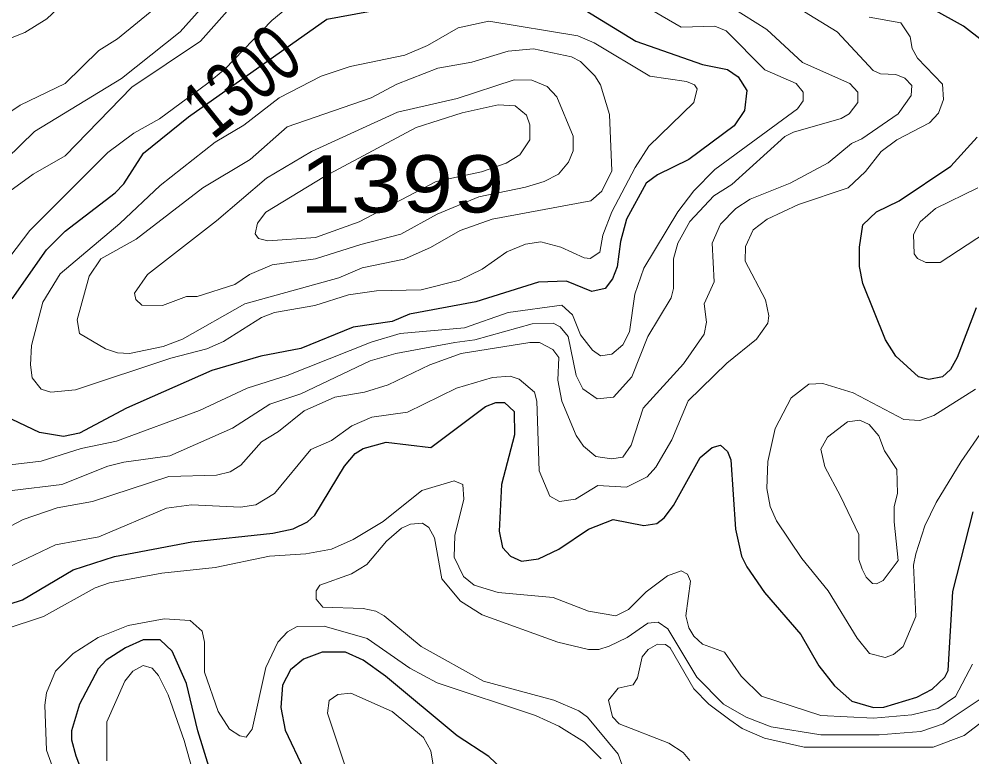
# Model space of a CAD drawing. Extents: x 577 to 602.9, y 7483.8 to 7511.6.
# Drawn here: x 580.554 to 581.886, y 7485.838 to 7486.869 of the extents above; entities that cross this region are included whole.
import ezdxf
from ezdxf.enums import TextEntityAlignment as Align

# ---------------------------------------------------------------- set-up
doc = ezdxf.new("R2010")
doc.units = 0
doc.header["$LTSCALE"] = 0.032
doc.layers.add('1', color=7, linetype='Continuous', lineweight=25)
doc.layers.add('2', color=7, linetype='Continuous', lineweight=13)
doc.layers.add('61', color=7, linetype='Continuous')

msp = doc.modelspace()

# ---------------------------------------------------------------- linework, layer by layer
at = {"layer": '1'}
for points in [[(581.3451, 7486.881), (581.4159, 7486.838), (581.5089, 7486.8054), (581.5439, 7486.7983), (581.559, 7486.7879), (581.5709, 7486.7688), (581.5677, 7486.741), (581.5534, 7486.7195), (581.4898, 7486.6726), (581.4461, 7486.6512), (581.4302, 7486.6392), (581.4031, 7486.5891), (581.3944, 7486.5581), (581.3896, 7486.5223), (581.3833, 7486.5056), (581.3729, 7486.4921), (581.3546, 7486.4881), (581.3189, 7486.5025), (581.2799, 7486.5009), (581.1924, 7486.4738), (581.0994, 7486.4563), (581.0755, 7486.446), (581.0207, 7486.438), (580.9475, 7486.4086), (580.8918, 7486.3975), (580.8235, 7486.3776), (580.7042, 7486.3251), (580.6382, 7486.2901), (580.6159, 7486.2854), (580.5825, 7486.2909), (580.5444, 7486.3092)], [(580.5444, 7486.4778), (580.5921, 7486.5462), (580.6183, 7486.5724), (580.6883, 7486.6257), (580.7002, 7486.6384), (580.728, 7486.6814), (580.7905, 7486.7319), (580.984, 7486.8685), (581.0421, 7486.8794)], [(581.9009, 7486.838), (581.8739, 7486.8587), (581.831, 7486.8826)], [(581.8914, 7486.4651), (581.8651, 7486.3959), (581.8556, 7486.3792), (581.8445, 7486.3689), (581.8254, 7486.3649), (581.8111, 7486.3689), (581.7793, 7486.3975), (581.765, 7486.4206), (581.7331, 7486.4993), (581.7284, 7486.5231), (581.7284, 7486.5502), (581.7331, 7486.5812), (581.7522, 7486.5995), (581.784, 7486.6146), (581.8564, 7486.6631), (581.893, 7486.7036)], [(580.4863, 7486.0341), (580.5587, 7486.0572), (580.6294, 7486.0993), (580.6875, 7486.1176), (580.7956, 7486.1383), (580.9085, 7486.1502), (580.9372, 7486.1566), (580.9571, 7486.1661), (580.9674, 7486.1756), (581.0087, 7486.244), (581.0238, 7486.2615), (581.035, 7486.2687), (581.0668, 7486.2774), (581.1296, 7486.2703), (581.2059, 7486.3275), (581.2203, 7486.3331), (581.2322, 7486.3331), (581.2457, 7486.3204), (581.2465, 7486.2878), (581.2282, 7486.2186), (581.225, 7486.1534), (581.2298, 7486.1303), (581.2409, 7486.1184), (581.256, 7486.1112), (581.2799, 7486.1144), (581.3085, 7486.1279), (581.3499, 7486.1558), (581.3841, 7486.1693), (581.427, 7486.1613), (581.4453, 7486.1637), (581.4556, 7486.1717), (581.4684, 7486.1892), (581.5057, 7486.256), (581.5224, 7486.2703), (581.5344, 7486.2734), (581.5439, 7486.2647), (581.5487, 7486.2528), (581.555, 7486.1558), (581.5638, 7486.1184), (581.5709, 7486.1033), (581.5956, 7486.0675), (581.6465, 7486.0087), (581.6719, 7485.9649), (581.6934, 7485.9371), (581.718, 7485.9156), (581.748, 7485.907), (581.7626, 7485.9075), (581.8087, 7485.9212), (581.8302, 7485.9323), (581.8476, 7485.949), (581.8524, 7485.9586), (581.8588, 7486.0691), (581.8874, 7486.1804)], [(580.8314, 7485.7852), (580.8036, 7485.8743), (580.7877, 7485.9403), (580.7678, 7485.9856), (580.7511, 7486.0015), (580.7272, 7486.0015), (580.7026, 7485.9904), (580.6756, 7485.9729), (580.6644, 7485.9609), (580.6382, 7485.9116), (580.6271, 7485.8743), (580.6271, 7485.8615), (580.6334, 7485.8393), (580.6644, 7485.7574)], [(581.2298, 7485.8202), (581.2107, 7485.8385), (581.1662, 7485.8671), (581.066, 7485.9506), (581.035, 7485.9729), (581.0103, 7485.984), (580.9777, 7485.984), (580.9515, 7485.9745), (580.9332, 7485.9594), (580.9221, 7485.9379), (580.9197, 7485.9069), (580.926, 7485.8751), (580.9515, 7485.821)]]:
    msp.add_lwpolyline(points, dxfattribs=at)
at = {"layer": '2'}
for points in [[(580.5364, 7487.2062), (580.5618, 7487.2054), (580.5817, 7487.1974), (580.5976, 7487.1784), (580.5992, 7487.1418), (580.604, 7487.1275), (580.6271, 7487.1036), (580.6692, 7487.0726), (580.7026, 7487.0599), (580.732, 7487.0551), (580.7789, 7487.0535), (580.8044, 7487.0472), (580.8243, 7487.0368), (580.8346, 7487.0249), (580.8378, 7487.0042), (580.829, 7486.9827), (580.7781, 7486.9167), (580.7424, 7486.8826), (580.6915, 7486.8412), (580.6652, 7486.8245), (580.6183, 7486.7784), (580.5555, 7486.7482), (580.4895, 7486.7036)], [(580.4784, 7486.8166), (580.5618, 7486.8499), (580.5929, 7486.869), (580.6294, 7486.904), (580.6438, 7486.9342), (580.6684, 7486.9676), (580.6692, 7486.9867), (580.6652, 7486.9994), (580.6461, 7487.0241), (580.6143, 7487.0503), (580.5881, 7487.0869), (580.5603, 7487.1147), (580.5467, 7487.1235)], [(580.9523, 7487.001), (580.8076, 7486.838), (580.7113, 7486.7736), (580.6183, 7486.6774), (580.5738, 7486.6519), (580.5308, 7486.6209)], [(581.4206, 7486.8913), (581.4795, 7486.8571), (581.5264, 7486.8587), (581.5423, 7486.8523), (581.5964, 7486.7975), (581.6401, 7486.7784), (581.6497, 7486.7665), (581.6497, 7486.7545), (581.6417, 7486.7434), (581.5264, 7486.6583), (581.497, 7486.6289), (581.4747, 7486.5995), (581.427, 7486.5207), (581.4143, 7486.4842), (581.4071, 7486.4317), (581.3976, 7486.4134), (581.3825, 7486.4007), (581.3666, 7486.3983), (581.3554, 7486.4062), (581.3387, 7486.4277), (581.3276, 7486.4555), (581.3125, 7486.4691), (581.2377, 7486.4587), (581.1765, 7486.4373), (581.0867, 7486.4293), (581.0461, 7486.4174), (580.9284, 7486.3705), (580.8728, 7486.353), (580.806, 7486.322), (580.6899, 7486.279), (580.6406, 7486.2687), (580.5849, 7486.2512), (580.5173, 7486.2432)], [(580.5213, 7486.5112), (580.569, 7486.5732), (580.6779, 7486.6822), (580.7145, 7486.7092), (580.7503, 7486.7291), (580.8177, 7486.7793), (580.8413, 7486.7987), (580.9071, 7486.8667), (580.9331, 7486.8881)], [(581.163, 7486.4166), (581.1908, 7486.4206), (581.2711, 7486.4428), (581.3006, 7486.4436), (581.3101, 7486.4388), (581.3212, 7486.4253), (581.3324, 7486.3705), (581.3419, 7486.3522), (581.3618, 7486.3379), (581.3849, 7486.3402), (581.4103, 7486.3689), (581.4326, 7486.4253), (581.4652, 7486.4794), (581.4684, 7486.4921), (581.4684, 7486.5335), (581.4747, 7486.5557), (581.4914, 7486.5859), (581.5248, 7486.6217), (581.5503, 7486.6376), (581.6242, 7486.7044), (581.6361, 7486.7108), (581.7029, 7486.7299), (581.7141, 7486.7362), (581.726, 7486.7521), (581.726, 7486.7665), (581.7149, 7486.7784), (581.6489, 7486.8078), (581.5988, 7486.8539), (581.5336, 7486.8953)], [(581.6433, 7486.8841), (581.6974, 7486.8507), (581.7475, 7486.7967), (581.7578, 7486.7919), (581.7793, 7486.7911), (581.792, 7486.7863), (581.8015, 7486.776), (581.8007, 7486.7617), (581.7824, 7486.7362), (581.7316, 7486.7013), (581.7172, 7486.6949), (581.6846, 7486.6679), (581.6314, 7486.6392), (581.5757, 7486.617), (581.5558, 7486.6042), (581.5344, 7486.582), (581.5224, 7486.5557), (581.5256, 7486.5017), (581.5113, 7486.4706), (581.5145, 7486.4452), (581.5113, 7486.4285), (581.4827, 7486.3872), (581.4262, 7486.3251), (581.4095, 7486.2734), (581.3976, 7486.2567), (581.3817, 7486.2544), (581.3602, 7486.2575), (581.3427, 7486.2719), (581.3324, 7486.287), (581.3125, 7486.3347), (581.3069, 7486.3641), (581.3085, 7486.3959), (581.2998, 7486.407), (581.2815, 7486.4166), (581.268, 7486.4166), (581.1717, 7486.4015)], [(580.5165, 7486.6543), (580.5754, 7486.7116), (580.697, 7486.7855), (580.7789, 7486.8507), (580.8068, 7486.8818)], [(581.6003, 7486.4436), (581.6019, 7486.454), (581.5972, 7486.4762), (581.5685, 7486.5303), (581.5693, 7486.551), (581.5797, 7486.574), (581.5996, 7486.5891), (581.6433, 7486.6098), (581.7125, 7486.6329), (581.7371, 7486.6559), (581.7586, 7486.6838), (581.7809, 7486.6997), (581.8262, 7486.7235), (581.8389, 7486.737), (581.8461, 7486.7561), (581.8445, 7486.7776), (581.8095, 7486.8142), (581.8023, 7486.8277), (581.7991, 7486.8436), (581.7864, 7486.8635), (581.7419, 7486.8714)], [(581.9303, 7486.5867), (581.8413, 7486.5287), (581.8214, 7486.5287), (581.8095, 7486.5343), (581.8047, 7486.5406), (581.8039, 7486.5677), (581.8135, 7486.5852), (581.8349, 7486.6042), (581.8938, 7486.6329)], [(580.5165, 7486.0921), (580.6048, 7486.1343), (580.6652, 7486.1454), (580.7598, 7486.1852), (580.7948, 7486.19), (580.8632, 7486.1868), (580.8847, 7486.19), (580.9109, 7486.2059), (580.9618, 7486.2671), (580.9904, 7486.2798), (581.0191, 7486.3005), (581.0469, 7486.3124), (581.097, 7486.3196), (581.1654, 7486.353), (581.2155, 7486.3681), (581.2401, 7486.3697), (581.2529, 7486.3657), (581.2743, 7486.3474), (581.2775, 7486.3347), (581.2807, 7486.2377), (581.2958, 7486.2019), (581.3093, 7486.1947), (581.3316, 7486.1979), (581.3626, 7486.217), (581.4031, 7486.2146), (581.4318, 7486.2289), (581.4437, 7486.2424), (581.466, 7486.2806), (581.489, 7486.3355), (581.5431, 7486.388), (581.5844, 7486.4213), (581.6003, 7486.4436)], [(580.5444, 7486.2098), (580.6135, 7486.2186), (580.6779, 7486.244), (580.7002, 7486.2496), (580.7646, 7486.2583), (580.8521, 7486.2973), (580.9046, 7486.3307), (580.9475, 7486.345), (581.0445, 7486.3911), (581.0803, 7486.4015), (581.163, 7486.4166)], [(581.1717, 7486.4015), (581.128, 7486.3856), (581.07, 7486.3577), (581.0366, 7486.3474), (580.9952, 7486.3402), (580.9523, 7486.3212), (580.9165, 7486.2925), (580.8926, 7486.2782), (580.864, 7486.2456), (580.8489, 7486.2361), (580.8298, 7486.2313), (580.763, 7486.2297), (580.6565, 7486.1947), (580.6072, 7486.186), (580.5595, 7486.1693), (580.4895, 7486.1327)], [(581.8906, 7486.3514), (581.8325, 7486.3148), (581.8127, 7486.3076), (581.7904, 7486.3092), (581.7196, 7486.3466), (581.6775, 7486.3593), (581.6576, 7486.3585), (581.633, 7486.3394), (581.6107, 7486.2965), (581.6003, 7486.2504), (581.5988, 7486.213), (581.6035, 7486.1876), (581.6123, 7486.1677), (581.6481, 7486.1152), (581.6846, 7486.0699), (581.7252, 7486.0039), (581.7427, 7485.9824), (581.7642, 7485.9768), (581.7761, 7485.9808), (581.7896, 7485.992), (581.8071, 7486.0341), (581.8039, 7486.1057), (581.8071, 7486.1216), (581.8198, 7486.1605), (581.8357, 7486.1931), (581.8707, 7486.2504), (581.9311, 7486.3379)], [(580.5332, 7486.0158), (580.5881, 7486.0341), (580.6605, 7486.0739), (580.6803, 7486.081), (580.7535, 7486.0945), (580.8282, 7486.1025), (580.9038, 7486.1184), (580.9547, 7486.1216), (580.9904, 7486.1279), (581.0207, 7486.1414), (581.0628, 7486.1669), (581.1169, 7486.2098), (581.1622, 7486.2233), (581.1741, 7486.2186), (581.1757, 7486.1979), (581.163, 7486.147), (581.1622, 7486.1168), (581.1749, 7486.0898), (581.19, 7486.0778), (581.2234, 7486.0675), (581.3006, 7486.0603), (581.3499, 7486.0413), (581.388, 7486.0349), (581.4055, 7486.0436), (581.4302, 7486.0683), (581.4604, 7486.0906), (581.4795, 7486.0977), (581.4882, 7486.0929), (581.4922, 7486.0834), (581.4858, 7486.0349), (581.4898, 7486.0182), (581.497, 7486.0063), (581.5089, 7485.9951), (581.5399, 7485.984), (581.563, 7485.9506), (581.5916, 7485.9228), (581.6743, 7485.8957), (581.7483, 7485.8918), (581.8015, 7485.8965), (581.8381, 7485.9053), (581.8628, 7485.922)], [(581.4047, 7485.8043), (581.3912, 7485.8417), (581.3483, 7485.8934), (581.3364, 7485.9021), (581.3014, 7485.9172), (581.2028, 7485.9434), (581.1161, 7485.992), (581.0644, 7486.0349), (581.0525, 7486.0413), (581.035, 7486.0452), (580.9785, 7486.0468), (580.969, 7486.058), (580.969, 7486.0699), (580.9745, 7486.0778), (581.0183, 7486.0937), (581.0398, 7486.1065), (581.0676, 7486.1391), (581.0883, 7486.1574), (581.101, 7486.1629), (581.1177, 7486.1645), (581.1264, 7486.1581), (581.1344, 7486.1438), (581.1447, 7486.0866), (581.171, 7486.0556), (581.2012, 7486.0365), (581.3069, 7485.9983), (581.3499, 7485.988), (581.3642, 7485.988), (581.3785, 7485.9927), (581.4039, 7486.0047), (581.4326, 7486.0246), (581.4469, 7486.0261), (581.4608, 7486.0167), (581.5014, 7485.949), (581.5383, 7485.9116), (581.5701, 7485.8934), (581.6051, 7485.8798), (581.6743, 7485.8687), (581.7562, 7485.8687), (581.8143, 7485.8735), (581.8453, 7485.8838), (581.9001, 7485.9204)], [(581.3674, 7485.8353), (581.3443, 7485.8584), (581.3085, 7485.8806), (581.2759, 7485.8957), (581.1384, 7485.9411), (581.1002, 7485.9617), (581.0405, 7486.0031), (580.9801, 7486.0206), (580.9427, 7486.0198), (580.9292, 7486.0126), (580.9157, 7485.9983), (580.899, 7485.9625), (580.8799, 7485.8767), (580.8712, 7485.8655), (580.8624, 7485.8671), (580.8481, 7485.8767), (580.8322, 7485.9013), (580.8131, 7485.9562), (580.8131, 7485.9983), (580.8099, 7486.0134), (580.7932, 7486.0285), (580.7567, 7486.0309), (580.7066, 7486.0214), (580.6644, 7486.0047), (580.6294, 7485.9824), (580.6048, 7485.9578), (580.5921, 7485.9275), (580.5897, 7485.9101), (580.5921, 7485.8472), (580.6072, 7485.8059)], [(581.9168, 7485.8997), (581.8747, 7485.8679), (581.8317, 7485.8512), (581.6512, 7485.8512), (581.5956, 7485.8639), (581.5646, 7485.8774), (581.5471, 7485.8894), (581.518, 7485.9117), (581.497, 7485.9328), (581.4639, 7485.99), (581.4574, 7485.995), (581.4463, 7485.9955), (581.4333, 7485.988), (581.4248, 7485.9774), (581.4183, 7485.9483), (581.4123, 7485.9383), (581.3912, 7485.9338), (581.3777, 7485.9172), (581.3832, 7485.8937), (581.3927, 7485.8841)], [(580.6764, 7485.8321), (580.6764, 7485.887), (580.7018, 7485.9434), (580.7129, 7485.9578), (580.7272, 7485.9657), (580.74, 7485.9617), (580.7487, 7485.9514), (580.7622, 7485.9244), (580.7845, 7485.8607), (580.8131, 7485.7598)], [(581.8628, 7485.922), (581.8866, 7485.9673)], [(581.0119, 7485.8178), (580.9849, 7485.8989), (580.9873, 7485.9164), (580.9992, 7485.9252), (581.0175, 7485.9267), (581.0755, 7485.9013), (581.1193, 7485.8647), (581.1296, 7485.8464), (581.1391, 7485.786)], [(581.3927, 7485.8841), (581.462, 7485.8568), (581.4819, 7485.8441), (581.4914, 7485.8329)]]:
    msp.add_lwpolyline(points, dxfattribs=at)
for points in [[(581.2831, 7486.5573), (581.3109, 7486.5502), (581.3435, 7486.5351), (581.3523, 7486.5343), (581.3658, 7486.543), (581.3697, 7486.5669), (581.3825, 7486.5995), (581.4151, 7486.6615), (581.4342, 7486.6909), (581.497, 7486.7521), (581.5017, 7486.7712), (581.4978, 7486.7768), (581.4866, 7486.7816), (581.4357, 7486.7887), (581.3578, 7486.8356), (581.3348, 7486.8452), (581.2107, 7486.8659), (581.1678, 7486.8563), (581.1248, 7486.8317), (581.093, 7486.8181), (581.0167, 7486.8022), (580.9761, 7486.7887), (580.9173, 7486.7585), (580.868, 7486.7203), (580.8282, 7486.6965), (580.7511, 7486.636), (580.6946, 7486.5828), (580.6112, 7486.5128), (580.5873, 7486.473), (580.5714, 7486.4126), (580.5698, 7486.3856), (580.5722, 7486.3673), (580.5849, 7486.3514), (580.5984, 7486.3474), (580.6326, 7486.3506), (580.7662, 7486.3951), (580.8163, 7486.4078), (580.8394, 7486.4182), (580.8926, 7486.4516), (580.9109, 7486.4587), (580.9674, 7486.4683), (581.0143, 7486.4834), (581.0533, 7486.4889), (581.1161, 7486.4905), (581.1694, 7486.504), (581.2012, 7486.5192), (581.2355, 7486.5436), (581.2616, 7486.5541)], [(581.0334, 7486.5212), (581.0008, 7486.5072), (580.8696, 7486.4706), (580.7821, 7486.4213), (580.7551, 7486.411), (580.7082, 7486.4015), (580.6915, 7486.4023), (580.6748, 7486.4078), (580.6382, 7486.4293), (580.635, 7486.4484), (580.6517, 7486.5096), (580.6684, 7486.5335), (580.7177, 7486.5613), (580.8107, 7486.6329), (580.8767, 7486.6726), (580.9284, 7486.7179), (581.0461, 7486.7585), (581.0819, 7486.7776), (581.1391, 7486.7999), (581.1869, 7486.8086), (581.2377, 7486.8237), (581.2727, 7486.8269), (581.326, 7486.8158), (581.3387, 7486.8094), (581.3586, 7486.7895), (581.3666, 7486.7768), (581.3793, 7486.7354), (581.3825, 7486.6567), (581.3682, 7486.6281), (581.353, 7486.6146), (581.2151, 7486.589), (581.1702, 7486.5733), (581.1288, 7486.5497), (581.0922, 7486.5333)], [(581.0314, 7486.5535), (580.9682, 7486.5335), (580.9078, 7486.5255), (580.8759, 7486.512), (580.8553, 7486.4977), (580.8028, 7486.481), (580.7877, 7486.481), (580.7543, 7486.4683), (580.7257, 7486.4691), (580.7169, 7486.477), (580.7153, 7486.4858), (580.7336, 7486.512), (580.8298, 7486.5867), (580.8998, 7486.6464), (580.9626, 7486.6838), (581.0827, 7486.7386), (581.1662, 7486.7577), (581.2457, 7486.7839), (581.2704, 7486.7832), (581.2918, 7486.7744), (581.3053, 7486.7601), (581.3284, 7486.7052), (581.3284, 7486.6846), (581.322, 7486.6686), (581.3077, 7486.6519), (581.2878, 7486.6416), (581.2616, 7486.6337), (581.1964, 7486.6201), (581.1384, 7486.5963), (581.0877, 7486.5679)], [(581.1368, 7486.6416), (581.2004, 7486.6551), (581.2346, 7486.6671), (581.2537, 7486.679), (581.268, 7486.6997), (581.268, 7486.7211), (581.2632, 7486.7346), (581.2473, 7486.7474), (581.2234, 7486.749), (581.1733, 7486.7378), (581.1089, 7486.7172), (580.9809, 7486.6488), (580.899, 7486.5987), (580.8871, 7486.5836), (580.8839, 7486.5685), (580.8887, 7486.5621), (580.9014, 7486.5589), (580.9682, 7486.5637), (581.0294, 7486.5852)], [(581.7021, 7486.2019), (581.7276, 7486.1486), (581.7276, 7486.1136), (581.7323, 7486.1001), (581.7379, 7486.089), (581.7467, 7486.0802), (581.7522, 7486.0794), (581.7618, 7486.0842), (581.7824, 7486.112), (581.7769, 7486.1661), (581.7769, 7486.1876), (581.7816, 7486.2059), (581.7809, 7486.2393), (581.7634, 7486.2655), (581.7554, 7486.2862), (581.7419, 7486.3021), (581.7292, 7486.3084), (581.7117, 7486.306), (581.6838, 7486.2846), (581.6743, 7486.2679), (581.6799, 7486.2432)]]:
    msp.add_lwpolyline(points, close=True, dxfattribs=at)

# ---------------------------------------------------------------- texts
at = {"layer": '61', "width": 0.7}
msp.add_text('1300', height=0.08, rotation=38.794, dxfattribs=at).set_placement((580.8897, 7486.7513), align=Align.CENTER)
at = {"layer": '61', "width": 1.2}
msp.add_text('1399', height=0.08, dxfattribs=at).set_placement((581.0892, 7486.5984), align=Align.CENTER)

doc.saveas('drawing.dxf')
